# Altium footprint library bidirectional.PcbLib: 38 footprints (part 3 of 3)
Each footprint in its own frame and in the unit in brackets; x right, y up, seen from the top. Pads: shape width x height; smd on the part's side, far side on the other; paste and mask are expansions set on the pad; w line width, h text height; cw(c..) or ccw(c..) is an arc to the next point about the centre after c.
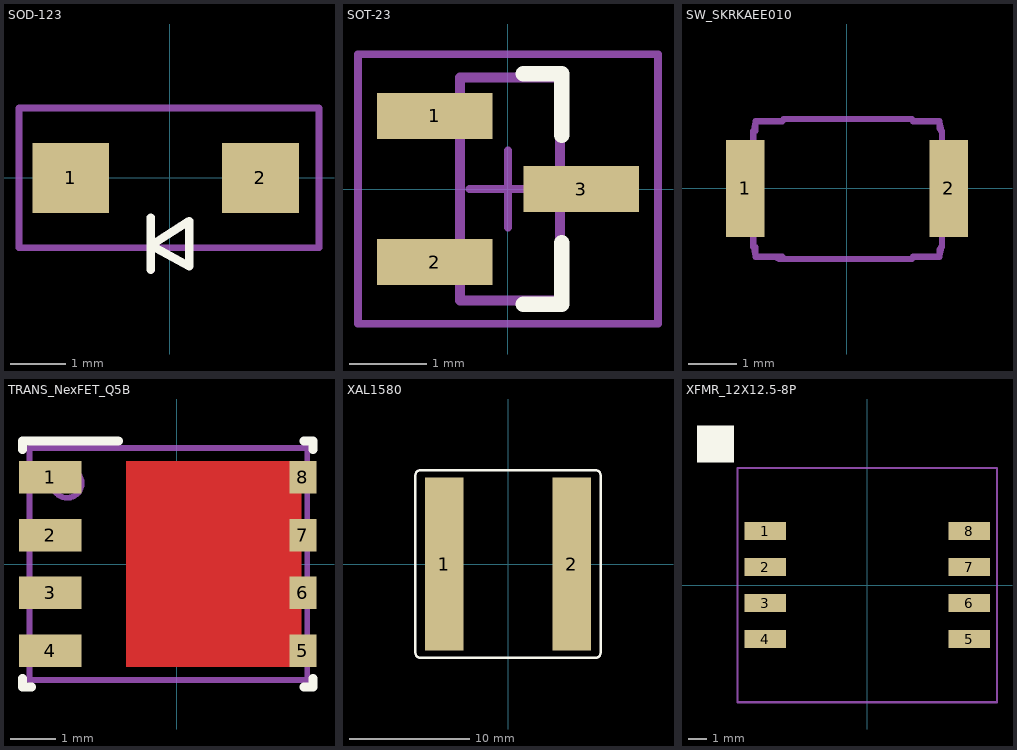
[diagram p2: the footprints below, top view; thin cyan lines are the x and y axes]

## SOD-123 [mil]
pads (2):
  rect 55x50 smd: 1(-71,0) 2(65,0)
Top Overlay:
  lines w6: -13.6,-65.8 -13.6,-28.3 ; -13.6,-48.3 13.9,-63.3 13.9,-30.8 -13.6,-48.3
Mechanical 5:
  lines w5: -13.2,-65.8 -13.2,-28.3 ; -108,-50 -108,50 107,50 107,-50 -108,-50 ; -13.2,-48.3 14.3,-63.3 14.3,-30.8 -13.2,-48.3
  text ".Designator" at -75,-15 h30

## SOT-23 [mm] "SOT23, 3-Leads, Body 2.9x1.3mm, Pitch 0.95mm, Lead Span 2.5mm, IPC Medium Density"
height 1.1
pads (3):
  rect 1.5x0.6 smd: 1(-0.95,0.95) 2(-0.95,-0.95) 3(0.95,0)
Top Overlay:
  lines w0.2: 0.2,-1.5 0.7,-1.5 0.7,-0.7 ; 0.2,1.5 0.7,1.5 0.7,0.7
Mechanical 5:
  lines w0.127: -1.16,-1.15 -1.16,-0.75 -0.625,-0.75 -0.625,0.75 -1.16,0.75 -1.16,1.15 -0.625,1.15 -0.625,1.45 0.675,1.45 0.675,0.2 1.21,0.2 1.21,-0.2 0.675,-0.2 0.675,-1.45 -0.625,-1.45 -0.625,-1.15 -1.16,-1.15
  text ".Designator" at -0.175,1.225 h0.76
Mechanical 15:
  lines w0.1: -0.5,0 0.5,0 ; 0,-0.5 0,0.5 ; -1.95,-1.75 1.95,-1.75 1.95,1.75 -1.95,1.75 -1.95,-1.75
3D body: height 1, standoff 0, extent -1.16,-1.45 1.21,1.45

## SW_SKRKAEE010 [mm] "Alps recommended land pattern"
height 2
pads (2):
  rect 0.8x2 smd: 1(-2.1,0) 2(2.1,0)
Mechanical 5:
  lines w0.127: -1.938,-1.211 -1.938,-0.811 -1.938,-0.394 ; -1.938,-0.711 -2.388,-0.711 -2.388,0.689 -1.938,0.689 ; -1.938,-0.336 -1.938,0.314 -1.938,0.372 -1.938,0.789 -1.938,1.189 ; -1.924,-1.211 -1.9,-1.348 -1.888,-1.346 ; -1.924,1.189 -1.9,1.326 -1.888,1.324 ; -1.888,-1.211 -1.888,-1.261 -1.888,-1.411 -1.338,-1.411 ; -1.888,1.189 -1.888,1.239 -1.888,1.389 -1.338,1.389 ; -1.481,-1.411 -1.462,-1.425 ccw(c-1.347,-1.261) -1.347,-1.461 ; -1.313,-1.461 1.337,-1.461 ; -1.313,1.439 1.337,1.439 ; 1.362,-1.411 1.912,-1.411 1.912,-1.261 ; 1.362,1.389 1.912,1.389 1.912,1.239 ; 1.912,-1.346 1.924,-1.348 1.949,-1.211 ; 1.912,1.324 1.924,1.326 1.949,1.189 ; 1.962,-1.211 1.962,-0.811 1.962,-0.394 ; 1.962,-0.711 2.412,-0.711 2.412,0.689 1.962,0.689 ; 1.962,-0.336 1.962,0.314 ; 1.962,0.372 1.962,0.789 1.962,1.189
  text ".Designator" at -1.397,-0.381 h0.76
3D body: height 1.96, standoff -0.04, extent -2.4,-1.45 2.4,1.45

## TRANS_NexFET_Q5B [mm] "TI recommended land pattern (nominal) November 2012"
height 1.05
pads (8):
  rect 1.372x0.71 smd paste-0.4: 1(-2.776,1.905) 2(-2.776,0.635) 3(-2.776,-0.635) 4(-2.776,-1.905)
  rect 0.59x0.71 smd paste-0.3: 5(2.776,-1.905) 6(2.776,-0.635) 7(2.776,0.635) 8(2.776,1.905)
Top Layer:
  rectangle: -1.106,-2.26 2.744,2.26
Top Overlay:
  lines w0.2: -3.385,-2.52 -3.385,-2.7 -3.185,-2.7 ; -3.385,2.52 -3.385,2.7 -1.28,2.7 ; 2.8,-2.7 3,-2.7 3,-2.52 ; 2.8,2.7 3,2.7 3,2.52
Top Paste:
  rectangle: 2.303,-2.159 3.069,-1.651
  rectangle: 2.303,-0.889 3.069,-0.381
  rectangle: 2.303,0.381 3.069,0.889
  rectangle: 2.303,1.651 3.069,2.159
  rectangle: -3.312,-2.186 -2.24,-1.624
  rectangle: -3.312,-0.916 -2.24,-0.354
  rectangle: -3.312,0.354 -2.24,0.916
  rectangle: -3.312,1.624 -2.24,2.186
  rectangle: 0.723,-1.942 2.017,-1.196
  region: 0.373,-1.196 -0.921,-1.196 -0.921,-1.942 0.373,-1.942
  rectangle: 0.723,1.196 2.017,1.942
  region: 0.373,1.942 -0.921,1.942 -0.921,1.196 0.373,1.196
  rectangle: 0.723,-0.896 2.017,-0.15
  region: 0.373,-0.15 -0.921,-0.15 -0.921,-0.896 0.373,-0.896
  region: 0.373,0.896 -0.921,0.896 -0.921,0.15 0.373,0.15
  rectangle: 0.723,0.15 2.017,0.896
Mechanical 5:
  circle w0.127: c-2.405,1.775 r0.32
  lines w0.127: -3.23,-2.55 2.875,-2.55 2.875,2.55 -3.23,2.55 -3.23,-2.55
  text ".Designator" at -2.085,-0.505 h1.02
3D body: height 1.05, standoff 0, extent -3.229,-2.549 2.874,2.549
3D body: height 1.06, standoff 1, extent -2.731,1.449 -2.079,2.101

## XAL1580 [mm] "COILCRAFT"
height 8
pads (2):
  rect 3.18x14.36 smd: 1(-5.3,0) 2(5.3,0)
Top Overlay:
  lines w0.2: -7.4,-7.8 7.4,-7.8 ; -7.3,-7.8 cw(c-7.3,-7.4) -7.7,-7.4 -7.7,7.4 cw(c-7.3,7.4) -7.3,7.8 7.3,7.8 cw(c7.3,7.4) 7.7,7.4 7.7,-7.4 cw(c7.3,-7.4) 7.3,-7.8
Mechanical 5:
  lines w0.1: -7.7,-7.4 ccw(c-7.3,-7.4) -7.3,-7.8 7.4,-7.8 ccw(c7.4,-7.5) 7.7,-7.5 7.7,7.4 ccw(c7.3,7.4) 7.3,7.8 -7.3,7.8 ccw(c-7.3,7.4) -7.7,7.4 -7.7,-7.4
  text ".Designator" at -2,-0.4 h0.76
3D body: height 8, standoff 0, extent -7.707,-7.807 7.707,7.807

## XFMR_12X12.5-8P [mm]
pads (8):
  rect 2.3x1 smd: 1(-5.65,3) 2(-5.65,1) 3(-5.65,-1) 4(-5.65,-3) 5(5.65,-3) 6(5.65,-1) 7(5.65,1) 8(5.65,3)
Top Overlay:
  region: -9.45,6.807 -7.418,6.807 -7.418,8.839 -9.45,8.839
Mechanical 5:
  lines w0.127: -7.2,-6.5 7.2,-6.5 7.2,6.5 -7.2,6.5 -7.2,-6.5
  text "*" at -6.002,4.797 h0.76
  text ".Designator" at -1.854,-0.508 h0.76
